
// ===== library: MasterCopy "IOL_INVENTORY" =====

FUNCTION_BLOCK "IOL_INVENTORY"   // FB1, SCL
TITLE = IOL_INVENTORY
{ S7_Optimized_Access := 'FALSE' }
FAMILY : S7-1200
VERSION : 1.0
// Inventory with IO-Link readers TN-M18-IOL-H1141 / TN-M30-IOL-H1141
// IO-Link V1.1
   VAR_INPUT
      Execute : Bool;   // 0 --> 1 : Sending command
      HwId : Hw_SubModule;   // Hardware identifier for the IO-Link master
      portAdr : Int;   // Start address for the read/write head
      TagNB : Byte;   // Index of the tag to be written in Data
   END_VAR
   VAR_OUTPUT
      Done : Bool;   // 0: The last command execution has not been completed. 1: Last command execution has been completed.
      Busy : Bool;   // 0: Function block is not active. 1: Function block is active
      Error : Bool;   // 0: No error. 1: Error
      Status : DWord;   // Error code. 0x00: No error. Error codes can be found in the "Reading Error Codes" section
      StatusWord AT Status : Array[0..1] of Word;
      "Tag present" : Bool;   // 0: No tags in the sensing range. 1: Tags in the sensing range
   END_VAR
   VAR_IN_OUT
      Data : Variant;   // Area of the control unit in which the data is stored.
   END_VAR
   VAR
      statStatusByte : Byte;   // First received Byte from IO-LINK Process Data Input
      statStatusBits AT statStatusByte : Array[0..7] of Bool;
      statPresence : Bool;
      statState : Int;
      statIdleState : Int;
      statTelegramState : Int := 1;
      statReadState : Int := 2;
      statErrorState : Int := 3;
      statExecuteReq : Bool;
      statDat : Array[0..9] of Byte;   // IO-LINK Process Data Output
      statRecDat : Array[0..8] of Byte;   // IO-LINK Process Data Input
      statAdrOffset : Int;
      statPresenceFF : Bool;
      InstTonrTime : TONR_TIME;
      statTimerIn : Bool;
      statTimerR : Bool;
      statTimerPt : Time := t#10ms;
      statReadData : Array[0..7] of Byte;
      statBusy : Bool;
      statDone : Bool;
      statReturnMoveBlkVar : Int;
      InstSetIoPart : SETIO_PART;
      statIoPartError : Bool;
      statIoPartStatus : DWord;
      InstGetIoPart : GETIO_PART;
      statInventory_En : Bool;
   END_VAR
   VAR_TEMP
      tempError : Bool;
      tempStatus : DWord;
      tempStatus_W AT tempStatus : Array[0..1] of Word;
   END_VAR
BEGIN
   #statAdrOffset := #portAdr;                             //start adress of port
   #InstGetIoPart(ID:=#HwId,
                  OFFSET:=#statAdrOffset,
                  LEN:=9,
                  STATUS=>#statIoPartStatus,
                  ERROR=>#statIoPartError,
                  INPUTS:=#statRecDat);

   #statStatusByte := #statRecDat[0];                       //Status Byte
   #statPresence := #statStatusBits[5];                     //Presence bit. Transponder on field
   #"Tag present" := #statPresence;

   IF NOT #Execute THEN
       #statDone := false;
       #statBusy := false;
       #Done := false;
       #Busy := false;
       #Error := false;
       #Status := 0;
   ELSE
       #Done := #statDone;
       #Busy := #statBusy;
   END_IF;

   IF #Execute AND #Execute <> #statExecuteReq THEN        //Positive edge for d#reading of data
       IF NOT #statBusy THEN
           #statBusy := TRUE;
           #statDone := FALSE;                                     //reset all the output parameters                                   
           #Error := FALSE;
           #Status := 0;
     //      #statOffset := 0;                                       //offset of puffer must be reseted
           #statState := #statReadState;                           //next step >> send read command
     //      #statCountCopy := 0;
       ELSE
           #tempStatus_W[1] := 16#8102;                            //block is still active
           #tempStatus_W[0] := 16#0001;                            //Error identifier for block errors
           #Status := #tempStatus;
           #statState := #statErrorState;
       END_IF;
   END_IF;
   #statExecuteReq := #Execute;
   //next step >> gather the scan UID data 
   #statPresenceFF := #"Tag present";

   //-----------------------------------------------------------------------------------------------------//
   //------------------------------------------start of state machine------------------------------------//
   //-----------------------------------------------------------------------------------------------------//
   CASE #statState OF
       0://IDLE
           #statBusy := false;
           #statTimerIn := false;
           FILL_BLK(IN := 0,
                    COUNT := CountOfElements(#Data),
                    OUT => #statReadData[0]);
           (*
           // #statAdr := 0;
           // #statDat[0] := 16#0;                      //Set read command
           // #statDat[2] := #statAdrRead[0];             //Adr-H
           // #statDat[3] := #statAdrRead[1];             //Adr-L
           // #InstSetIoPart(ID:=#hwId,
           //                OFFSET:=#statAdrOffset,
           //                LEN:=8,
           //                STATUS=>#statIoPartStatus,
           //                ERROR=>#statIoPartError,
           //                OUTPUTS:=#statDat);
           *)
           //-------------------------------------------------Scan UID Mode------------------------------------------//
           //--------------------------------------------- Get The Scan UID Dateâ ---------------------------------------//
           //-----------------------------------------------------------------------------------------------------//

       2://SCAN_UID_state

           IF #statStatusBits[5] THEN
               #statDat[0] := #TagNB;
               #InstSetIoPart(ID := #HwId,
                              OFFSET := #statAdrOffset,
                              LEN := 10,
                              STATUS => #statIoPartStatus,
                              ERROR => #statIoPartError,
                              OUTPUTS := #statDat);
               IF #statIoPartError THEN
                   #tempStatus_W[1] := DWORD_TO_WORD(#statIoPartStatus);   //Error has to BLKMOV occured
                   #tempStatus_W[0] := 16#0001;                            //functions-Error identifier
                   #Status := #tempStatus;
                   #statState := #statErrorState;
               END_IF;
           END_IF;

           //Add a timer before moving the UID data into the Output Register
           IF NOT #statInventory_En THEN
               #statTimerIn := true;                              //wait 10 msec
               #statTimerR := false;
           END_IF;
           IF #statInventory_En THEN
               //-------------------------- Scan UID Data is ready ------------------------------------------------//
               #statReturnMoveBlkVar := MOVE_BLK_VARIANT(SRC := #statRecDat,
                                                         COUNT := 8,
                                                         SRC_INDEX := 1,
                                                         DEST_INDEX := 0,
                                                         DEST => #statReadData);
               IF #statReturnMoveBlkVar = 0 THEN
                   #statDat[0] := #TagNB;
               END_IF;

               VariantPut(SRC := #statReadData,
                          DST := #Data);
               #statState := #statIdleState;
               #statBusy := FALSE;
               #statDone := TRUE;
           END_IF;

           //------------------------------------------------------------------------------------------------------------//
           //-------------------------------------------------Error state------------------------------------------------//
           //---------------------------------------------error has occured----------------------------------------------//

       3://Error_State
           #tempError := TRUE;
           #statBusy := FALSE;
           #Error := #tempError;
           #statDone := FALSE;
           #statTimerIn := FALSE;
           #statTimerR := TRUE;
           #statState := #statIdleState;
   END_CASE;

   //------------------------------------------------------------------------------------------------------------//
   //-------------------------------------------------Timer------------------------------------------------------//
   //------------------------------------------------------------------------------------------------------------//

   #InstTonrTime(IN := #statTimerIn,                  //this timer will start, if the tag has left the antenna field
                           R := #statTimerR,
                           PT := #statTimerPt);
   IF #InstTonrTime.Q THEN                           //error has occured. No tag on field during the 5 sec.
       #tempStatus_W[1] := 16#8101;                           //tag has left the field
       #tempStatus_W[0] := 16#0001;                           //Error identifier for block errors
       #Status := #tempStatus;
       #statState := #statErrorState;
       #statInventory_En:=TRUE;
       #statTimerIn := FALSE;                              //reset Timer
       #statTimerR := TRUE;
   END_IF;
END_FUNCTION_BLOCK

// ===== library: MasterCopy "IOL_CONTINUOUS_READ" =====

FUNCTION_BLOCK "IOL_CONTINUOUS_READ"   // FB2, SCL
TITLE = IOL_CONTINUOUS_READ
{ S7_Optimized_Access := 'FALSE' }
FAMILY : S7-1200
VERSION : 1.0
// Scan 32/64 bits of User Data with IO-Link readers TN-M18-IOL-H1141 / TN-M30-IOL-H1141
// IO-Link V1.1
   VAR_INPUT
      Execute : Bool;   // 0 --> 1 : Sending command
      HwId : Hw_SubModule;   // Hardware identifier for the IO-Link master
      portAdr : Int;   // Start address for the read/write head
   END_VAR
   VAR_OUTPUT
      Done : Bool;   // 0: The last command execution has not been completed. 1: Last command execution has been completed.
      Busy : Bool;   // 0: Function block is not active. 1: Function block is active
      Error : Bool;   // 0: No error. 1: Error
      Status : DWord;   // Error code. 0x00: No error. Error codes can be found in the "Reading Error Codes" section
      statusWord AT Status : Array[0..1] of Word;
      "Tag present" : Bool;   // 0: No tags in the sensing range. 1: Tags in the sensing range
   END_VAR
   VAR_IN_OUT
      Data : Variant;   // Area of the control unit in which the data is stored.
   END_VAR
   VAR
      statPae : Array[0..7] of Byte;
      statStatusByte : Byte;   // First received Byte from IO-LINK Process Data Input
      statStatusBits AT statStatusByte : Array[0..7] of Bool;
      statPresence : Bool;
      statState : Int;
      statIdleState : Int;
      statTelegramState : Int := 1;
      statReadState : Int := 2;
      statErrorState : Int := 3;
      statAdrRead : Byte;
      statOffset : Int;
      statExecuteReq : Bool;
      statLength : DInt;
      statDat : Array[0..9] of Byte;   // IO-LINK Process Data Output
      statRecDat : Array[0..8] of Byte;   // IO-LINK Process Data Input
      statAdrOffset : Int;
      statPresenceFF : Bool;
      InstTonrTime : TONR_TIME;
      statTimerIn : Bool;
      statTimerR : Bool;
      statTimerPt : Time := t#5s;
      statReadData : Array[0..7] of Byte;
      statCountCopy : DInt;
      statBusy : Bool;
      statDone : Bool;
      statReturnMoveBlkVar : Int;
      statDiffTo4 : Int;
      statDiffTo8 : Int;
      InstSetIoPart : SETIO_PART;
      statIoPartError : Bool;
      statIoPartStatus : DWord;
      InstGetIoPart : GETIO_PART;
      statBLKMOV_En : Bool;
   END_VAR
   VAR_TEMP
      tempError : Bool;
      tempStatus : DWord;
      tempStatus_W AT tempStatus : Array[0..1] of Word;
   END_VAR
BEGIN
   #statAdrOffset := #portAdr;                             //start adress of port
   #InstGetIoPart(ID:=#HwId,
                  OFFSET:=#statAdrOffset,
                  LEN:=9,
                  STATUS=>#statIoPartStatus,
                  ERROR=>#statIoPartError,
                  INPUTS:=#statRecDat);

   #statStatusByte := #statRecDat[0];                       //Status Byte
   #statPresence := #statStatusBits[5];                     //Presence bit. Transponder on field
   #"Tag present" := #statPresence;

   IF NOT #Execute THEN
       #statDone := false;
       #statBusy := false;
       #Done := false;
       #Busy := false;
       #Error := false;
       #Status := 0;
   ELSE
       #Done := #statDone;
       #Busy := #statBusy;
   END_IF;

   IF #Execute AND #Execute <> #statExecuteReq THEN        //Positive edge for d#reading of data
       IF NOT #statBusy THEN
          // #statAdrRead := WORD_TO_BYTE(#adrTag);                  //Transponder Address
          // #statDiffTo4 := WORD_TO_INT(#length) MOD 4;
          // #statDiffTo8 := WORD_TO_INT(#length) MOD 8;
          // #statLength := #length;                                 //Length of read Dat
           #statBusy := TRUE;
           #statDone := FALSE;                                     //reset all the output parameters                                   
           #Error := FALSE;
           #Status := 0;
           #statOffset := 0;                                       //offset of puffer must be reseted
           #statState := #statReadState;                           //next step >> send read command
           #statCountCopy := 0;
       ELSE
           #tempStatus_W[1] := 16#8102;                            //block is still active
           #tempStatus_W[0] := 16#0001;                            //Error identifier for block errors
           #Status := #tempStatus;
           #statState := #statErrorState;
       END_IF;

   END_IF;
   #statExecuteReq := #Execute;
   //next step >> gather the scan User data 
   #statPresenceFF := #"Tag present";

   //-----------------------------------------------------------------------------------------------------//
   //------------------------------------------start of state machine------------------------------------//
   //-----------------------------------------------------------------------------------------------------//
   CASE #statState OF
       0://IDLE
           #statBusy := FALSE;
           #statTimerIn := FALSE;
           FILL_BLK(IN := 0,
                    COUNT := CountOfElements(#Data),
                    OUT => #statReadData[0]);
           (*
           // #statAdr := 0;
           // #statDat[0] := 16#0;                      //Set read command
           // #statDat[2] := #statAdrRead[0];             //Adr-H
           // #statDat[3] := #statAdrRead[1];             //Adr-L
           // #InstSetIoPart(ID:=#hwId,
           //                OFFSET:=#statAdrOffset,
           //                LEN:=8,
           //                STATUS=>#statIoPartStatus,
           //                ERROR=>#statIoPartError,
           //                OUTPUTS:=#statDat);
           *)
           //-------------------------------------------------Scan User Mode ------------------------------------------//
           //---------------------------------------------Scan_User_State ---------------------------------------//
           //-----------------------------------------------------------------------------------------------------//

       2://Scan_User_State
           IF #statStatusBits[5] THEN
               IF #statStatusBits[6] THEN                                  //IF RFID error has occured
                   #tempStatus_W[1] := #statRecDat[1];                     //error_RFID
                   #tempStatus_W[0] := 16#0011;                            //Error identifier for RFID errors
                   #Status := #tempStatus;
                   #statState := #statErrorState;
               END_IF;
               //For a 32 bits memory based transponder (EXT=0)
               IF #statStatusBits[7] AND NOT #statStatusBits[6] AND NOT #statStatusBits[0] THEN
                   #statReturnMoveBlkVar := MOVE_BLK_VARIANT(SRC := #statRecDat,
                                                             COUNT := 4,
                                                             SRC_INDEX := 1,
                                                             DEST_INDEX := #statOffset,
                                                             DEST => #statReadData);

               END_IF;
               //For a 64 bits memory based transponder (EXT=1)
               IF #statStatusBits[7] AND NOT #statStatusBits[6] AND #statStatusBits[0] THEN
                   #statReturnMoveBlkVar := MOVE_BLK_VARIANT(SRC := #statRecDat,
                                                             COUNT := 8,
                                                             SRC_INDEX := 1,
                                                             DEST_INDEX := #statOffset,
                                                             DEST => #statReadData);

               END_IF;
               IF #statReturnMoveBlkVar = 0 THEN
                   VariantPut(SRC := #statReadData,
                              DST := #Data);
                   #statState := #statIdleState;
                   #statBusy := FALSE;
                   #statDone := TRUE;
               END_IF;
           END_IF;

           //------------------------------------------------------------------------------------------------------------//
           //-------------------------------------------------Error state------------------------------------------------//
           //---------------------------------------------error has occured----------------------------------------------//

       3://Error_State
           #tempError := TRUE;
           #statBusy := FALSE;
           #Error := #tempError;
           #statDone := FALSE;
           #statTimerIn := FALSE;
           #statTimerR := TRUE;
           #statState := #statIdleState;
   END_CASE;

   //------------------------------------------------------------------------------------------------------------//
   //-------------------------------------------------Timer------------------------------------------------------//
   //------------------------------------------------------------------------------------------------------------//

   #InstTonrTime(IN := #statTimerIn,                  //this timer will start, if the tag has left the antenna field
                           R := #statTimerR,
                           PT := #statTimerPt);
   IF #InstTonrTime.Q THEN                           //error has occured. No tag on field during the 5 sec.
       #tempStatus_W[1] := 16#8101;                           //tag has left the field
       #tempStatus_W[0] := 16#0001;                           //Error identifier for block errors
       #Status := #tempStatus;
       #statState := #statErrorState;
   END_IF;
END_FUNCTION_BLOCK

// ===== library: MasterCopy "IOL_READ" =====

FUNCTION_BLOCK "IOL_READ"   // FB3, SCL
TITLE = IOL_READ
{ S7_Optimized_Access := 'FALSE' }
FAMILY : S7-1200
VERSION : 1.0
// Read Data with IO-Link readers TN-M18-IOL-H1141 / TN-M30-IOL-H1141
// IO-Link V1.1
   VAR_INPUT
      Execute : Bool;   // 0 --> 1 : Sending command
      AdrTag : Word;   // The block address of the memory area to be read.
      Length : Word;   // The length of the data to be read (bytes).
      HwId : Hw_SubModule;   // Hardware identifier for the IO-Link master
      portAdr : Int;   // Start address for the read/write head
   END_VAR
   VAR_OUTPUT
      Done : Bool;   // 0: The last command execution has not been completed. 1: Last command execution has been completed.
      Busy : Bool;   // 0: Function block is not active. 1: Function block is active
      Error : Bool;   // 0: No error. 1: Error
      Status : DWord;   // Error code. 0x00: No error. Error codes can be found in the "Reading Error Codes" section
      statusWord AT Status : Array[0..1] of Word;
      "Tag present" : Bool;   // 0: No tags in the sensing range. 1: Tags in the sensing range
   END_VAR
   VAR_IN_OUT
      Data : Variant;   // Area of the control unit in which the data is stored.
   END_VAR
   VAR
      statPae : Array[0..7] of Byte;
      statStatusByte : Byte;   // First received Byte from IO-LINK Process Data Input
      statStatusBits AT statStatusByte : Array[0..7] of Bool;
      statPresence : Bool;
      statState : Int;
      statIdleState : Int;
      statTelegramState : Int := 1;
      statReadState : Int := 2;
      statErrorState : Int := 3;
      statAdrRead : Byte;
      statOffset : Int;
      statExecuteReq : Bool;
      statLength : DInt;
      statDat : Array[0..9] of Byte;   // IO-LINK Process Data Output
      statRecDat : Array[0..8] of Byte;   // IO-LINK Process Data Input
      statAdrOffset : Int;
      statPresenceFF : Bool;
      InstTonrTime : TONR_TIME;
      statTimerIn : Bool;
      statTimerR : Bool;
      statTimerPt : Time := t#5s;
      statReadData : Array[0..1999] of Byte;
      statCountCopy : DInt;
      statBusy : Bool;
      statDone : Bool;
      statReturnMoveBlkVar : Int;
      statDiffTo4 : Int;
      statDiffTo8 : Int;
      InstSetIoPart : SETIO_PART;
      statIoPartError : Bool;
      statIoPartStatus : DWord;
      InstGetIoPart : GETIO_PART;
      statBLKMOV_En : Bool;
   END_VAR
   VAR_TEMP
      tempError : Bool;
      tempStatus : DWord;
      tempStatus_W AT tempStatus : Array[0..1] of Word;
   END_VAR
BEGIN
   #statAdrOffset := #portAdr;                             //start adress of port
   #InstGetIoPart(ID:=#HwId,
                  OFFSET:=#statAdrOffset,
                  LEN:=9,
                  STATUS=>#statIoPartStatus,
                  ERROR=>#statIoPartError,
                  INPUTS:=#statRecDat);

   #statStatusByte := #statRecDat[0];//Status Byte
   #statPresence := #statStatusBits[5];                     //Presence bit. Transponder on field
   #"Tag present" := #statPresence;

   IF NOT #Execute THEN
       #statDone := false;
       #statBusy := false;
       #Done := false;
       #Busy := false;
       #Error := false;
       #Status := 0;
   ELSE
       #Done := #statDone;
       #Busy := #statBusy;
   END_IF;

   IF #Execute AND #Execute <> #statExecuteReq THEN        //Positive edge for d#reading of data
       IF NOT #statBusy THEN
           #statAdrRead := WORD_TO_BYTE(#AdrTag);                  //Transponder Address
           #statDiffTo4 := WORD_TO_INT(#Length) MOD 4;
           #statDiffTo8 := WORD_TO_INT(#Length) MOD 8;
           #statLength := #Length;                                 //Length of read Dat
           #statBusy := TRUE;
           #statDone := FALSE;                                     //reset all the output parameters                                   
           #Error := FALSE;
           #Status := 0;
           #statOffset := 0;                                       //offset of puffer must be reseted
           #statState := #statReadState;                           //next step >> send read command
           #statCountCopy := 0;
       ELSE
           #tempStatus_W[1] := 16#8102;                            //block is still active
           #tempStatus_W[0] := 16#0001;                            //Error identifier for block errors
           #Status := #tempStatus;
           #statState := #statErrorState;
       END_IF;
       IF #Length < 0 THEN
           #tempStatus_W[1] := 16#8104;                             //length too short
           #tempStatus_W[0] := 16#0001;                             //Error identifier for block errors
           #Status := #tempStatus;
           #statState := #statErrorState;
       END_IF;
   END_IF;
   #statExecuteReq := #Execute;
   //next step >> send read command

   IF NOT #"Tag present" AND #"Tag present" <> #statPresenceFF THEN   //the tag has left the antenna  field
       IF NOT #statDone THEN
           #statTimerIn := true;                              //wait 5 sec
           #statTimerR := false;
       END_IF;
   END_IF;
   #statPresenceFF := #"Tag present";
   IF #"Tag present" THEN
       #statTimerR := true;
       #statTimerIn := false;
   END_IF;
   //-----------------------------------------------------------------------------------------------------//
   //------------------------------------------start of state machine------------------------------------//
   //-----------------------------------------------------------------------------------------------------//
   CASE #statState OF
       0://IDLE
           #statBusy := false;
           #statTimerIn := false;
           FILL_BLK(IN := 0,
                    COUNT := CountOfElements(#Data),
                    OUT => #statReadData[0]);
           (*
           // #statAdr := 0;
           // #statDat[0] := 16#0;                      //Set read command
           // #statDat[2] := #statAdrRead[0];             //Adr-H
           // #statDat[3] := #statAdrRead[1];             //Adr-L
           // #InstSetIoPart(ID:=#hwId,
           //                OFFSET:=#statAdrOffset,
           //                LEN:=8,
           //                STATUS=>#statIoPartStatus,
           //                ERROR=>#statIoPartError,
           //                OUTPUTS:=#statDat);
           *)
           //-------------------------------------------------Read state------------------------------------------//
           //---------------------------------------------sent read command---------------------------------------//
           //-----------------------------------------------------------------------------------------------------//

       2://Read_state

           IF #statLength > 0 AND NOT #statStatusBits[7]  THEN
               #statDat[1] := #statAdrRead;                   // Start Adr2Read into Tag
               #statDat[0] := 16#82;                          // Set read command
               #statBLKMOV_En := TRUE;                    // Reset BLKMOV flag
           END_IF;

           IF NOT #statIoPartError THEN
               #statState := #statTelegramState;                           //Telegram: Edit the read data
           END_IF;


           //-----------------------------------------------Telegram state----------------------------------------//
           //---------------------------------------------edit received data--------------------------------------//
           //-----------------------------------------------------------------------------------------------------//  

       1://Telegram_state

           IF #statLength > 0 THEN                      //Only when length of data>0 can continue  
               IF #statStatusBits[6] THEN                                   //IF RFID error has occured
                   #tempStatus_W[1] := #statRecDat[1];    //error_RFID
                   #tempStatus_W[0] := 16#0011;                            //Error identifier for RFID errors
                   #Status := #tempStatus;
                   #statState := #statErrorState;
               END_IF;
               //-------------------------- read command is ready for a 32 bits based Memory Transponder (EXT=0)------------------------------------------------//

               IF #statStatusBits[7] AND NOT #statStatusBits[0]  THEN
                   IF NOT #statIoPartError THEN
                       IF #statLength >= 4 THEN
                           #statState := #statReadState;
                           #statCountCopy := 4;
                       ELSE
                           IF #statDiffTo4 <> 0 THEN
                               #statCountCopy := #statDiffTo4;
                               #statAdrRead := #statAdrRead + 1;
                               #statState := #statReadState;
                           ELSE
                               #statCountCopy := 4;
                               #statAdrRead := #statAdrRead + 1;
                               #statState := #statReadState;
                           END_IF;
                       END_IF;
                       IF #statStatusBits[7] AND NOT #statStatusBits[6] AND #statBLKMOV_En THEN
                          #statReturnMoveBlkVar := MOVE_BLK_VARIANT(SRC := #statRecDat,
                                                                     COUNT := DINT_TO_UDINT(#statCountCopy),
                                                                     SRC_INDEX := 1,
                                                                     DEST_INDEX := #statOffset,
                                                                     DEST => #statReadData);
                           IF #statReturnMoveBlkVar = 0 THEN
                               #statOffset := #statOffset + 4;
                               #statLength := #statLength - 4;
                               #statAdrRead := #statAdrRead + 1; //Increase the read address value of transponder memory
                               #statBLKMOV_En := FALSE;
                               #statDat[0] := 00;
                           END_IF;
                       ELSE
                           #statState := #statIdleState;
                       END_IF;
                   ELSE
                       #tempStatus_W[1] := DWORD_TO_WORD(#statIoPartStatus);           //Error has to BLKMOV occured
                       #tempStatus_W[0] := 16#0001;                                    //functions-Error identifier
                       #Status := #tempStatus;
                       #statState := #statErrorState;
                   END_IF;
               END_IF;


               //-------------------------- read command is ready for a 64 bits based Memory Transponder (EXT=1)------------------------------------------------//

               IF #statStatusBits[7] AND #statStatusBits[0]  THEN
                   IF NOT #statIoPartError THEN
                       IF #statLength >= 8 THEN
                           #statState := #statReadState;
                           #statCountCopy := 8;
                       ELSE
                           IF #statDiffTo8 <> 0 THEN
                               #statCountCopy := #statDiffTo8;
                               #statAdrRead := #statAdrRead + 1;
                               #statState := #statReadState;
                           ELSE
                               #statCountCopy := 8;
                               #statAdrRead := #statAdrRead + 1;
                               #statState := #statReadState;
                           END_IF;
                       END_IF;
                       IF #statStatusBits[7] AND NOT #statStatusBits[6] AND #statBLKMOV_En THEN
                          #statReturnMoveBlkVar := MOVE_BLK_VARIANT(SRC := #statRecDat,
                                                                     COUNT := DINT_TO_UDINT(#statCountCopy),
                                                                     SRC_INDEX := 1,
                                                                     DEST_INDEX := #statOffset,
                                                                     DEST => #statReadData);
                           IF #statReturnMoveBlkVar = 0 THEN
                               #statOffset := #statOffset + 8;
                               #statLength := #statLength - 8;
                               #statAdrRead := #statAdrRead + 1; //Increase the read address value of transponder memory
                               #statBLKMOV_En := FALSE;
                               #statDat[0] := 00;
                           END_IF;
                       ELSE
                           #statState := #statIdleState;
                       END_IF;
                   ELSE
                       #tempStatus_W[1] := DWORD_TO_WORD(#statIoPartStatus);           //Error has to BLKMOV occured
                       #tempStatus_W[0] := 16#0001;                                    //functions-Error identifier
                       #Status := #tempStatus;
                       #statState := #statErrorState;
                   END_IF;
               END_IF;

               #InstSetIoPart(ID:=#HwId,
                              OFFSET:=#statAdrOffset,
                              LEN:=10,
                              STATUS=>#statIoPartStatus,
                              ERROR=>#statIoPartError,
                              OUTPUTS:=#statDat);

               IF #statIoPartError THEN
                   #tempStatus_W[1] := DWORD_TO_WORD(#statIoPartStatus);   //Error has to BLKMOV occured
                   #tempStatus_W[0] := 16#0001;                            //functions-Error identifier
                   #Status := #tempStatus;
                   #statState := #statErrorState;
               END_IF;
               #statState := #statReadState;
           ELSE
               VariantPut(SRC := #statReadData,
                          DST := #Data);
               #statState := #statIdleState;
               #statBusy := FALSE;
               #statDone := TRUE;
           END_IF;

           //------------------------------------------------------------------------------------------------------------//
           //-------------------------------------------------Error state------------------------------------------------//
           //---------------------------------------------error has occured----------------------------------------------//

       3://Error_State
           #tempError := TRUE;
           #statBusy := FALSE;
           #Error := #tempError;
           #statDone := FALSE;
           #statTimerIn := FALSE;
           #statTimerR := TRUE;
           #statState := #statIdleState;
   END_CASE;

   //------------------------------------------------------------------------------------------------------------//
   //-------------------------------------------------Timer------------------------------------------------------//
   //------------------------------------------------------------------------------------------------------------//

   #InstTonrTime(IN := #statTimerIn,                  //this timer will start, if the tag has left the antenna field
                           R := #statTimerR,
                           PT := #statTimerPt);
   IF #InstTonrTime.Q THEN                           //error has occured. No tag on field during the 5 sec.
       #tempStatus_W[1] := 16#8101;                           //tag has left the field
       #tempStatus_W[0] := 16#0001;                           //functions-Error identifier
       #Status := #tempStatus;
       #statState := #statErrorState;
   END_IF;
END_FUNCTION_BLOCK

// ===== library: MasterCopy "IOL_WRITE" =====

FUNCTION_BLOCK "IOL_WRITE"   // FB4, SCL
TITLE = IOL_WRITE
{ S7_Optimized_Access := 'FALSE' }
FAMILY : S7-1200
VERSION : 1.0
// Write data with IO-Link readers TN-M18-IOL-H1141 / TN-M30-IOL-H1141
// IO-Link V1.1
   VAR_INPUT
      Execute : Bool;   // 0 --> 1 : Sending command
      AdrTag : Word;   // The block address of the memory area to be written.
      Length : Word;   // The length of the data to be written (bytes).
      HwId : Hw_SubModule;   // Hardware identifier for the IO-Link master
      portAdr : Int;   // Start Address of the Process Data Input / Output registers
      "32/64bits" : Bool;   // 0: Write 32 bytes 1: Write 64 bytes
   END_VAR
   VAR_OUTPUT
      Done : Bool;   // 0: The last command execution has not been completed. 1: Last command execution has been completed.
      Busy : Bool;   // 0: Function block is not active. 1: Function block is active
      Error : Bool;   // 0: No error. 1: Error
      Status : DWord;   // Error code. 0x00: No error. Error codes can be found in the "Reading Error Codes" section
      statusWord AT Status : Array[0..1] of Word;
      "Tag present" : Bool;   // 0: No tags in the sensing range. 1: Tags in the sensing range
   END_VAR
   VAR_IN_OUT
      Data : Variant;   // Area of the control unit in which the data is stored.
   END_VAR
   VAR
      instTonR : TONR_TIME;   // Timer 2
      statState : Int;   // Current state
      statTimerIn : Bool;   // Timer 2 parameters
      statTimerR : Bool;
      statTimerPt : Time := T#5s;
      statTelegramState : Int := 1;   // Edit state
      statWriteState : Int := 2;   // Write Command state
      statErrorState : Int := 3;   // Error state
      statIdleState : Int;   // first state
      statAdrOffset : Int;
      statStatusByte : Byte;   // First received Byte from IO-LINK Process Data Input
      statStatusBits AT statStatusByte : Array[0..7] of Bool;
      statDat : Array[0..9] of Byte;   // IO-LINK Process Data Output
      statRecDat : Array[0..8] of Byte;   // IO-LINK Process Data Input
      statPresenceBit : Bool;   // Presence bit
      statExecuteReq : Bool;
      statLength : DInt;
      statAdrWrite : Byte;
      statWriteOffset : Int;
      statPresenceFf : Bool;
      statWriteData : Array[0..1999] of Byte;
      statBytemove : Int;
      statDone : Bool;
      statBusy : Bool;
      InstSetIoPart : SETIO_PART;
      statIoPartError : Bool;
      statIoPartStatus : DWord;
      InstGetIoPart : GETIO_PART;
      statReturnMoveBlkVar : Int;
      statWriteCMDResetEn : Bool;
   END_VAR
   VAR_TEMP
      tempError : Bool;
      tempStatus : DWord;
      tempStatus_W AT tempStatus : Array[0..1] of Word;
   END_VAR
   // start values inside typed variables
   // statRecDat[2] := 16#ff;
   // statRecDat[3] := 16#ff;
BEGIN
   #statAdrOffset := #portAdr;                         //start adress of port
   #InstGetIoPart(ID := #HwId,                         //read data from process image
                  OFFSET := #statAdrOffset,
                  LEN := 9,
                  STATUS => #statIoPartStatus,
                  ERROR => #statIoPartError,
                  INPUTS := #statRecDat);

   #statStatusByte := #statRecDat[0];                  //Status Byte
   #statPresenceBit := #statStatusBits[5];             //Presence bit. Transponder on field
   #"Tag present" := #statPresenceBit;

   IF NOT #Execute THEN
       #statDone := false;
       #statBusy := false;
       #Done := false;
       #Busy := false;
       #Error := false;
       #Status := 0;
   ELSE
       #Done := #statDone;
       #Busy := #statBusy;
   END_IF;

   IF #Execute AND #Execute <> #statExecuteReq THEN        //Positive edge for writing of data
       IF NOT #statBusy THEN                             
           #statAdrWrite := WORD_TO_BYTE(#AdrTag);         //Transponder Address
           #statLength := #Length;                         //Length of read Data
           #statState := #statWriteState;
           #statBusy := TRUE;
           #statDone := FALSE;                             //Reset all the output parameters                                   
           #Error := FALSE;
           #Status := 0;
           #statWriteOffset := 0;
           #statBytemove := 0;
           VariantGet(SRC := #Data,
                      DST => #statWriteData);
           //next step >> send write command
       ELSE
           #tempStatus_W[1] := 16#8102;                          //block is still active
           #tempStatus_W[0] := 16#0001;                          //Error identifier for block errors
           #Status := #tempStatus;
           #statState := #statErrorState;
       END_IF;
       IF #Length < 4 THEN
           #tempStatus_W[1] := 16#8104;                          //Length too short
           #tempStatus_W[0] := 16#0011;                          //Identifier rfid errors
           #Status := #tempStatus;
           #statState := #statErrorState;
       END_IF;
   END_IF;
   #statExecuteReq := #Execute;

   IF NOT #"Tag present" AND #"Tag present" <> #statPresenceFf THEN        //The tag has left the antenna  field
       IF NOT #statDone THEN
           #statTimerIn := true;                                 //Wait 5 sec
           #statTimerR := false;
       END_IF;
   END_IF;
   #statPresenceFf := #"Tag present";
   IF #"Tag present" THEN
       #statTimerR := true;
       #statTimerIn := false;
   END_IF;
   //-----------------------------------------------------------------------------------------------------//
   //------------------------------------------start of state machine------------------------------------//
   //-----------------------------------------------------------------------------------------------------//
   CASE #statState OF
       0://IDLE
           #statWriteOffset := 0;                                  //Offset of buffer must be reset
           #statBusy := false;
           #statTimerIn := false;

           //-------------------------------------------------Write state-----------------------------------------//
           //---------------------------------------------send write command--------------------------------------//
           //-----------------------------------------------------------------------------------------------------//

       2://Write_state
           // For a 32 bits memory based transponders
           IF #statLength > 0 AND NOT #statStatusBits[7] AND NOT #statWriteCMDResetEn AND NOT #"32/64bits"  THEN
               #statReturnMoveBlkVar := MOVE_BLK_VARIANT(SRC := #statWriteData,
                                                         COUNT := 4,
                                                         SRC_INDEX := #statWriteOffset,
                                                         DEST_INDEX := 2,
                                                         DEST => #statDat);
               //Update the Process Data Output Buffer with new values to write on the transponder           
               #statDat[1] := #statAdrWrite;                       // Set Adr2Write into Tag
               #statDat[0] := 16#84;                               // Set write command
               #statWriteCMDResetEn := TRUE;
           END_IF;
           // For a 64 bits memory based transponders
           IF #statLength > 0 AND NOT #statStatusBits[7] AND NOT #statWriteCMDResetEn AND #"32/64bits" THEN
               #statReturnMoveBlkVar := MOVE_BLK_VARIANT(SRC := #statWriteData,
                                                         COUNT := 8,
                                                         SRC_INDEX := #statWriteOffset,
                                                         DEST_INDEX := 2,
                                                         DEST => #statDat);
               //Update the Process Data Output Buffer with new values to write on the transponder           
               #statDat[1] := #statAdrWrite;                       // Set Adr2Write into Tag
               #statDat[0] := 16#85;                               // Set write command
               #statWriteCMDResetEn := TRUE;
           END_IF;
           IF NOT #statIoPartError THEN
               #statState := #statTelegramState;                   // Telegram: Edit the write data
           END_IF;

           //-----------------------------------------------Telegram state----------------------------------------//
           //-----------------------------------------------------------------------------------------------------//
           //-----------------------------------------------------------------------------------------------------//  

       1://Telegram_state

           IF #statLength > 0 THEN                                     //Only when length of data>0 can continue  
               IF #statStatusBits[6] THEN                              //IF RFID error has occured
                   #tempStatus_W[1] := #statRecDat[1];
                   #tempStatus_W[0] := 16#0011;                        //Error identifier for RFID errors
                   #Status := #tempStatus;
                   #statState := #statErrorState;
               END_IF;

               //-------------------------- write command is ready for a 32 bits based Memory Transponder (EXT=0)------------------------------------------------//

                   IF NOT #statIoPartError THEN
                       IF #statStatusBits[7] AND NOT #statStatusBits[6] AND #statWriteCMDResetEn AND NOT #"32/64bits"  THEN
                           #statDat[0] := 00;      // Reset Write CMD
                           #statAdrWrite := #statAdrWrite + 1;
                           #statLength := #statLength - 4;
                           #statWriteOffset := #statWriteOffset + 4;
                           #statWriteCMDResetEn := FALSE;
                           #statState := #statWriteState;
                       ELSE
                           #statState := #statIdleState;
                       END_IF;

                  ELSE
                       #tempStatus_W[1] := DWORD_TO_WORD(#statIoPartStatus);     //Error has to BLKMOV occured
                       #tempStatus_W[0] := 16#0001;                              //Functions-Error identifier
                       #Status := #tempStatus;
                       #statState := #statErrorState;
                   END_IF;

              //-------------------------- write command is ready for a 64 bits based Memory Transponder (EXT=1)------------------------------------------------//

                  IF NOT #statIoPartError THEN
                      IF #statStatusBits[7] AND NOT #statStatusBits[6] AND #statWriteCMDResetEn AND #"32/64bits" THEN
                          #statDat[0] := 00;       // Reset Write CMD
                          #statAdrWrite := #statAdrWrite + 1;
                          #statLength := #statLength - 8;
                          #statWriteOffset := #statWriteOffset + 8;
                          #statWriteCMDResetEn := FALSE;
                          #statState := #statWriteState;
                      ELSE
                          #statState := #statIdleState;
                      END_IF;

                  ELSE
                      #tempStatus_W[1] := DWORD_TO_WORD(#statIoPartStatus);            // Error has to BLKMOV occured
                      #tempStatus_W[0] := 16#0001;                                     // Functions-Error identifier
                      #Status := #tempStatus;
                      #statState := #statErrorState;
                  END_IF;

               #InstSetIoPart(ID := #HwId,
                              OFFSET := #statAdrOffset,
                              LEN := 10,
                              STATUS => #statIoPartStatus,
                              ERROR => #statIoPartError,
                              OUTPUTS := #statDat);

               IF #statIoPartError THEN
                   #tempStatus_W[1] := DWORD_TO_WORD(#statIoPartStatus);               // Error has to BLKMOV occured
                   #tempStatus_W[0] := 16#0001;                                        // Functions-Error identifier
                   #Status := #tempStatus;
                   #statState := #statErrorState;
               END_IF;
               #statState := #statWriteState;
           ELSE
               #statState := #statIdleState;
               #statBusy := FALSE;
               #statDone := TRUE;
           END_IF;



           //------------------------------------------------------------------------------------------------------------//
           //-------------------------------------------------Error state------------------------------------------------//
           //---------------------------------------------error has occured----------------------------------------------//

       3://Error_State
           #tempError := TRUE;
           #statBusy := FALSE;
           #Error := #tempError;
           #statDone := FALSE;
           #statTimerIn := FALSE;
           #statTimerR := TRUE;
           #statState := #statIdleState;
   END_CASE;


   //------------------------------------------------------------------------------------------------------------//
   //-------------------------------------------------Timer------------------------------------------------------//
   //------------------------------------------------------------------------------------------------------------//

   #instTonR(IN := #statTimerIn,                                   //this timer will start, if the tag has left the antenna field
                           R := #statTimerR,
                           PT := #statTimerPt);
   IF #instTonR.Q THEN                                             // Error has occured. No tag on field during the 5 sec.
       #tempStatus_W[1] := 16#8101;                                // Tag has left the field
       #tempStatus_W[0] := 16#0001;                                //functions-Error identifier
       #Status := #tempStatus;
       #statState := #statErrorState;
   END_IF;
END_FUNCTION_BLOCK

// ===== library: MasterCopy "IOL_HF-READ-WRITE-HEAD_SWITCH_OFF" =====

FUNCTION_BLOCK "IOL_HF-READ-WRITE-HEAD_SWITCH_OFF"   // FB5, SCL
TITLE = IOL_HF-READ-WRITE-HEAD_SWITCH_OFF
{ S7_Optimized_Access := 'FALSE' }
FAMILY : S7-1200
VERSION : 1.0
// Set Antenna with IO-Link reader TN-M18-IOL-H1141 / TN-M30-IOL-H1141
// IO-Link V1.1
   VAR_INPUT
      Execute : Bool;   // 0 --> 1 : Sending command
      antenna : Bool;   // 0: Switch off the antenna 1: Switch on the antennas
      HwId : Hw_SubModule;   // Hardware identifier for the IO-Link master
      portAdr : Int;   // Start address for the read/write head
   END_VAR
   VAR_OUTPUT
      Done : Bool;   // 0: The last command execution has not been completed. 1: Last command execution has been completed.
      Busy : Bool;   // 0: Function block is not active. 1: Function block is active
      Error : Bool;   // 0: No error. 1: Error
      Status : DWord;   // Error code. 0x00: No error. Error codes can be found in the "Reading Error Codes" section
      statusWord AT Status : Array[0..1] of Word;
      "Tag present" : Bool;   // 0: No tags in the sensing range. 1: Tags in the sensing range
   END_VAR
   VAR
      statExecuteReq : Bool;   // positive edge og execute
      statAntByte : Byte;   // Byte 0, PDI Header byte
      statAntBit AT statAntByte : Array[0..7] of Bool;
      statState : Int;   // current state
      statLastState : Int;   // last state
      statAntennaOn : Int := 1;   // On state
      statAntennaOff : Int := 2;   // OFF state
      statReadyState : Int := 3;
      statRecDat : Array[0..8] of Byte;   // received buffer
      statAdrOffset : Int;   // step for FOR
      statDat : Array[0..9] of Byte;   // sent buffer
      statPresenceBit : Bool;
      statBusy : Bool;
      InstSetIoPart : SETIO_PART;
      statIoPartError : Bool;
      statIoPartStatus : DWord;
      InstGetIoPart : GETIO_PART;
   END_VAR
   VAR_TEMP
      tempDone : Bool;
      tempError : Bool;
      tempStatus : DWord;
      tempStatus_W AT tempStatus : Array[0..1] of Word;
   END_VAR
BEGIN
   #statAdrOffset:=#portAdr;                                //start adress of port
   #InstGetIoPart(ID := #HwId,                              //read data from process image
                  OFFSET := #statAdrOffset,
                  LEN := 9,
                  STATUS => #statIoPartStatus,
                  ERROR => #statIoPartError,
                  INPUTS := #statRecDat);
   #statAntByte:=#statRecDat[0];                  //status byte
   #statPresenceBit := #statAntBit[5];                 //Presence bit. Transponder on field
   #"Tag present" := #statPresenceBit;
   #Busy := #statBusy;

   //------------------------------------If error byte<>0--------------------------------------------------//
   //------------------------------------save the rfid error-----------------------------------------------//

   IF #statRecDat[1]<>0 AND #statBusy THEN
     #statAntByte:=#statRecDat[1];  
      #statusWord[1]:=BYTE_TO_WORD(#statAntByte);    //error_BLK
      #statusWord[0]:=16#0011;                    //identifier rfid errors
      #statBusy := FALSE;
      #Done := FALSE;
      #Error:=TRUE;
      #statState:=0;
   END_IF;

   IF NOT #Execute THEN
       #Done := FALSE;
       #Error := FALSE;
       #Status := 0;
   END_IF;

   IF #Execute AND #Execute<>#statExecuteReq THEN //Positive Edge for antenna on
     #statLastState:=0;
     #statBusy:=TRUE;                              //Block active
     #Done:=FALSE;                             //reset all output parameters
     #Error:=FALSE;
     #Status:=0;
     IF #antenna THEN                          //if antenna then activate the ANTENNA_ON process
       #statState:=#statAntennaOn;
     ELSIF NOT #antenna THEN                   //if not antenna then activate the ANTENNA_OFF process 
       #statState:=#statAntennaOff;
     END_IF;

   END_IF;
   #statExecuteReq:=#Execute;


   //---------------------------------------Antenna on state-----------------------------------------------//
   //---------------------------------------Reset Antenna bit----------------------------------------------//

   CASE #statState OF
       0:  //Idle
           ;
       1:  //Antenna_on
                                                        //Antenna on process
           #statAntBit[4] := FALSE;                        //Reset Byte 0, bit 4
           #statDat[0] := 16#0;
           #statLastState := #statAntennaOn;
           #InstSetIoPart(ID := #HwId,                         //Write data into process image
                          OFFSET := #statAdrOffset,
                          LEN := 10,
                          STATUS => #statIoPartStatus,
                          ERROR => #statIoPartError,
                          OUTPUTS := #statDat);
           IF NOT #statIoPartError AND #statRecDat[1] = 0 THEN
               #statState := #statReadyState;
           ELSIF #statIoPartError THEN
               #tempError := true;
               #Error := #tempError;                             //error has occured
               #statBusy := FALSE;
               #tempStatus_W[1] := DWORD_TO_WORD(#statIoPartStatus);//error_BLK
               #tempStatus_W[0] := 16#0001;                    //identifier block errors
           END_IF;
       2:
                                                      //Antenna off process
           #statAntBit[4] := true;                         //set Byte 0, bit 4
           #statDat[0] := 16#10;
           #statLastState := #statAntennaOff;
           #InstSetIoPart(ID := #HwId,                         //Write data into process image
                          OFFSET := #statAdrOffset,
                          LEN := 10,
                          STATUS => #statIoPartStatus,
                          ERROR => #statIoPartError,
                          OUTPUTS := #statDat);
           IF NOT #statIoPartError AND #statRecDat[1] = 0 THEN
               IF #statAntByte = 16#10 THEN                    //if status_byte=16#10 then antenna off
                   #statState := #statReadyState;
               END_IF;
           ELSIF #statIoPartError THEN
               #tempError := true;
               #Error := #tempError;                              //Error has occured
               #statBusy := FALSE;
               #tempStatus_W[1] := DWORD_TO_WORD(#statIoPartStatus);//error_BLK
               #tempStatus_W[0] := 16#0001;                     //identifier block errors
           END_IF;
       3:
           #tempDone := true;
           #Done := #tempDone;                           //Ready
           #statBusy := FALSE;
           #statState := 0;
   END_CASE;
END_FUNCTION_BLOCK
